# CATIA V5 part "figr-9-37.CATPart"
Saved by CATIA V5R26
Part number: Part1
Bounding box of the stored display mesh (mm): x 0 to 200, y -70 to 70, z -70 to 70
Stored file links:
  D:\_Deepak\CATIA\CATIA V5-6R2016_Deepak\Resources\Part files\Partfiles\c09_catia_v5_6r2016_prt\figr-9-37.CATPart
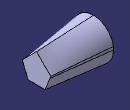
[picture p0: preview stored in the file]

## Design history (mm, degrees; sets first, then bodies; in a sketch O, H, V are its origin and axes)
Set1
  Plane1: type Offset, RefPlane yz-plane, Offset 200
Body1 (main body)
  Sketch1 on yz-plane, origin (0, 0, 0), H (0, 1, 0), V (0, 0, 1)
    circle A1 centre (0, 0) radius 70
    point P1 (70, 0)
    point P2 (-48.9898, -50)
    point P3 (48.9898, -50)
    point P4 (69.282, 10)
    point P5 (-69.282, 10)
    point P6 (0, 70)
    radius A1 = 70
    coincidence: A1 P1, P1 H, P2 A1, P3 A1, P4 A1, P5 A1, P6 V
  Sketch2 on Plane1, origin (200, 0, 0), H (0, 1, 0), V (0, 0, 1)
    point P1 (-30, -40)
    line L1 (-30, -40) -> (30, -40)
    point P2 (30, -40)
    line L2 (30, -40) -> (50, 10)
    point P3 (50, 10)
    line L3 (50, 10) -> (0, 60)
    point P4 (0, 60)
    line L4 (0, 60) -> (-50, 10)
    point P5 (-50, 10)
    line L5 (-50, 10) -> (-30, -40)
    horizontal: L1 H
    coincidence: P4 V
    symmetry: P3 P5 V, P2 P1 V
  Loft1: Sections (edge of Sketch1; Sketch2), SectionCouplingPoints ({coupling CouplingPoints (vertex of Sketch1; vertex [element of Sketch2 | element of Sketch2])}; {coupling CouplingPoints (vertex of Sketch1; vertex [element of Sketch2 | element of Sketch2])}; {coupling CouplingPoints (vertex of Sketch1; vertex [element of Sketch2 | element of Sketch2])}; {coupling CouplingPoints (vertex of Sketch1; vertex [element of Sketch2 | element of Sketch2])})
